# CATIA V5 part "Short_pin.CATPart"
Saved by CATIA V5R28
Part number: Short_pin
Bounding box of the stored display mesh (mm): x -15 to 15, y -15 to 15, z 0 to 60
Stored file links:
  E:\Back up\Mission d'enseignement\TP Catia\2 oct - Assemblage\Short_pin.CATPart
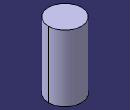
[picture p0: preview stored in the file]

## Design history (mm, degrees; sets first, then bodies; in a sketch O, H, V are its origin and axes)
Body1 (main body)
  Sketch1 on xy-plane, origin (0, 0, 0), H (1, 0, 0), V (0, 1, 0)
    circle A1 centre (0, 0) radius 15
    radius A1 = 15
  Pad1: profile Sketch1, direction (0, 0, 1), length 60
